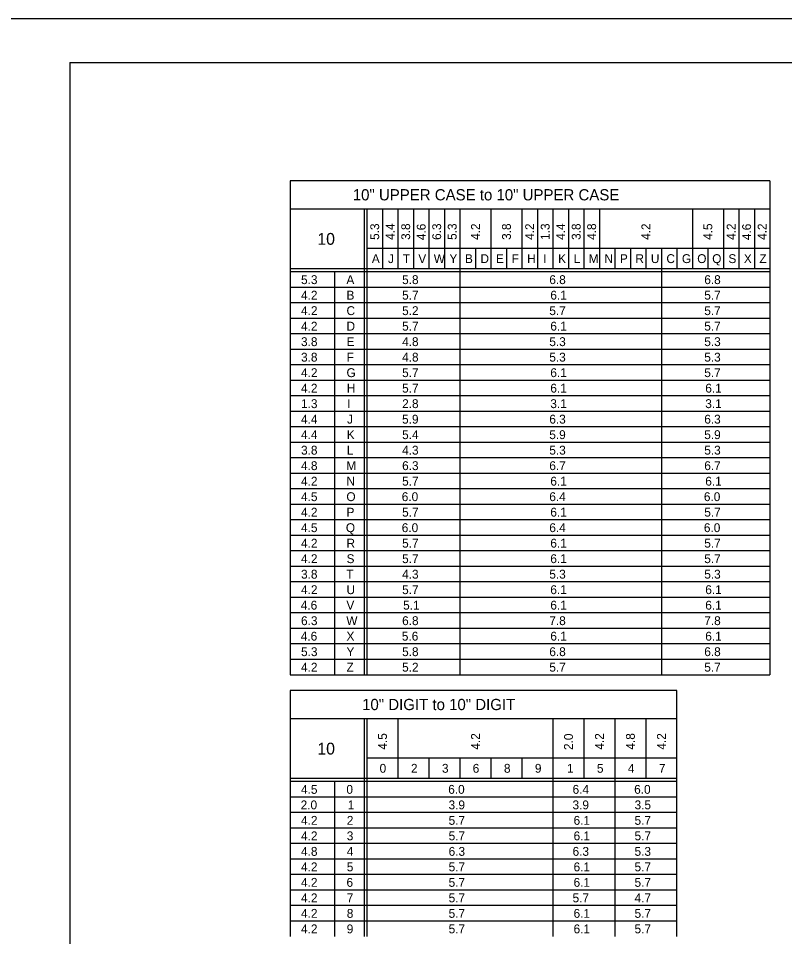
# Model space of a CAD drawing. Extents: x 637580 to 641849, y 297270 to 299646.
# Drawn here: x 640966.8 to 641226.4, y 299334.6 to 299645.6 of the extents above; entities that cross this region are included whole.
import ezdxf

# ---------------------------------------------------------------- set-up
doc = ezdxf.new("R2010")
doc.units = 0
for name, color, linetype in [('1', 7, 'Continuous'), ('2', 7, 'Continuous'), ('XCS-GRID-HVGL', 7, 'Continuous')]:
    doc.layers.add(name, color=color, linetype=linetype)

msp = doc.modelspace()

# ---------------------------------------------------------------- linework, layer by layer
at = {"layer": '1'}
for q in [(641770.31, 299630.63), (640984.31, 299066.63)]:
    msp.add_line((640984.31, 299630.63), q, dxfattribs=at)
at = {"layer": '2'}
for p, q in [((641221.44, 299590.63), (641058.94, 299590.63)), ((641058.94, 299590.63), (641058.94, 299423.25)), ((641221.44, 299590.63), (641221.44, 299423.25)), ((641058.94, 299581.13), (641221.44, 299581.13)), ((641083.94, 299581.13), (641083.94, 299423.25)), ((641084.94, 299581.13), (641084.94, 299423.25)), ((641090.19, 299581.13), (641090.19, 299560.75)), ((641095.44, 299581.13), (641095.44, 299560.75)), ((641100.69, 299581.13), (641100.69, 299560.75)), ((641105.94, 299581.13), (641105.94, 299560.75)), ((641111.19, 299581.13), (641111.19, 299560.75)), ((641116.44, 299581.13), (641116.44, 299423.25)), ((641126.94, 299581.13), (641126.94, 299560.75)), ((641137.44, 299581.13), (641137.44, 299560.75)), ((641142.69, 299581.13), (641142.69, 299560.75)), ((641147.94, 299581.13), (641147.94, 299560.75)), ((641153.19, 299581.13), (641153.19, 299560.75)), ((641158.44, 299581.13), (641158.44, 299560.75)), ((641163.69, 299581.13), (641163.69, 299560.75)), ((641195.19, 299581.13), (641195.19, 299560.75)), ((641205.69, 299581.13), (641205.69, 299560.75)), ((641210.94, 299581.13), (641210.94, 299560.75)), ((641216.19, 299581.13), (641216.19, 299560.75)), ((641084.94, 299567.75), (641221.44, 299567.75)), ((641121.69, 299567.75), (641121.69, 299560.75)), ((641132.19, 299567.75), (641132.19, 299560.75)), ((641168.94, 299567.75), (641168.94, 299560.75)), ((641174.19, 299567.75), (641174.19, 299560.75)), ((641179.44, 299567.75), (641179.44, 299560.75)), ((641179.44, 299567.75), (641179.44, 299560.75)), ((641184.69, 299567.75), (641184.69, 299423.25)), ((641189.94, 299567.75), (641189.94, 299560.75)), ((641200.44, 299567.75), (641200.44, 299560.75)), ((641221.44, 299560.75), (641058.94, 299560.75)), ((641221.44, 299559.75), (641058.94, 299559.75)), ((641073.94, 299559.75), (641073.94, 299423.25)), ((641221.44, 299554.5), (641058.94, 299554.5)), ((641221.44, 299549.25), (641058.94, 299549.25)), ((641221.44, 299544), (641058.94, 299544)), ((641221.44, 299538.75), (641058.94, 299538.75)), ((641221.44, 299533.5), (641058.94, 299533.5)), ((641221.44, 299528.25), (641058.94, 299528.25)), ((641221.44, 299523), (641058.94, 299523)), ((641221.44, 299517.75), (641058.94, 299517.75)), ((641221.44, 299512.5), (641058.94, 299512.5)), ((641221.44, 299507.25), (641058.94, 299507.25)), ((641221.44, 299502), (641058.94, 299502)), ((641221.44, 299496.75), (641058.94, 299496.75)), ((641221.44, 299491.5), (641058.94, 299491.5)), ((641221.44, 299486.25), (641058.94, 299486.25)), ((641221.44, 299481), (641058.94, 299481)), ((641221.44, 299475.75), (641058.94, 299475.75)), ((641221.44, 299470.5), (641058.94, 299470.5)), ((641221.44, 299465.25), (641058.94, 299465.25)), ((641221.44, 299460), (641058.94, 299460)), ((641221.44, 299454.75), (641058.94, 299454.75)), ((641221.44, 299449.5), (641058.94, 299449.5)), ((641221.44, 299444.25), (641058.94, 299444.25)), ((641221.44, 299439), (641058.94, 299439)), ((641221.44, 299433.75), (641058.94, 299433.75)), ((641221.44, 299428.5), (641058.94, 299428.5)), ((641058.94, 299423.25), (641058.94, 299423.25)), ((641058.94, 299423.25), (641221.44, 299423.25)), ((641189.94, 299418), (641058.94, 299418)), ((641058.94, 299418), (641058.94, 299334.63)), ((641189.94, 299334.63), (641189.94, 299418)), ((641058.94, 299408.5), (641189.94, 299408.5)), ((641083.94, 299408.5), (641083.94, 299334.63)), ((641084.94, 299408.5), (641084.94, 299334.63)), ((641095.44, 299408.5), (641095.44, 299388.13)), ((641147.94, 299408.5), (641147.94, 299334.63)), ((641158.44, 299408.5), (641158.44, 299388.13)), ((641168.94, 299408.5), (641168.94, 299334.63)), ((641179.44, 299408.5), (641179.44, 299388.13)), ((641084.94, 299395.13), (641189.94, 299395.13)), ((641105.94, 299395.13), (641105.94, 299388.13)), ((641116.44, 299395.13), (641116.44, 299388.13)), ((641126.94, 299395.13), (641126.94, 299388.13)), ((641137.44, 299395.13), (641137.44, 299388.13)), ((641189.94, 299388.13), (641058.94, 299388.13)), ((641189.94, 299387.13), (641058.94, 299387.13)), ((641073.94, 299387.13), (641073.94, 299334.63)), ((641189.94, 299381.88), (641058.94, 299381.88)), ((641189.94, 299376.63), (641058.94, 299376.63)), ((641189.94, 299371.38), (641058.94, 299371.38)), ((641189.94, 299366.13), (641058.94, 299366.13)), ((641189.94, 299360.88), (641058.94, 299360.88)), ((641189.94, 299355.63), (641058.94, 299355.63)), ((641189.94, 299350.38), (641058.94, 299350.38)), ((641189.94, 299345.13), (641058.94, 299345.13)), ((641189.94, 299339.88), (641058.94, 299339.88))]:
    msp.add_line(p, q, dxfattribs=at)
at = {"layer": 'XCS-GRID-HVGL'}
msp.add_lwpolyline([(640944.31, 299645.63), (641785.31, 299645.63), (641785.31, 299051.63), (640944.31, 299051.63)], close=True, dxfattribs=at)

# ---------------------------------------------------------------- texts
at = {"layer": '2'}
for s, height, p in [('10" UPPER CASE to 10" UPPER CASE', 3.8, (641080.12, 299583.98)), ('10', 4, (641068.13, 299568.94)), ('A', 3, (641086.58, 299562.75)), ('J', 3, (641092.07, 299562.75)), ('T', 3, (641097.07, 299562.75)), ('V', 3, (641102.33, 299562.75)), ('W', 3, (641107.56, 299562.75)), ('Y', 3, (641112.87, 299562.75)), ('B', 3, (641118.13, 299562.75)), ('D', 3, (641123.38, 299562.75)), ('E', 3, (641128.64, 299562.75)), ('F', 3, (641133.95, 299562.75)), ('H', 3, (641139.21, 299562.75)), ('I', 3, (641144.63, 299562.75)), ('K', 3, (641149.71, 299562.75)), ('L', 3, (641154.96, 299562.75)), ('M', 3, (641160.06, 299562.75)), ('N', 3, (641165.38, 299562.75)), ('P', 3, (641170.63, 299562.75)), ('R', 3, (641175.88, 299562.75)), ('U', 3, (641181.12, 299562.75)), ('C', 3, (641186.38, 299562.75)), ('G', 3, (641191.63, 299562.75)), ('O', 3, (641196.83, 299562.75)), ('Q', 3, (641201.9, 299562.75)), ('S', 3, (641207.39, 299562.75)), ('X', 3, (641212.62, 299562.75)), ('Z', 3, (641217.88, 299562.75)), ('5.3', 3, (641062.59, 299555.63)), ('A', 3, (641077.96, 299555.63)), ('5.8', 3, (641096.84, 299555.63)), ('6.8', 3, (641146.71, 299555.63)), ('6.8', 3, (641199.21, 299555.63)), ('4.2', 3, (641062.59, 299550.38)), ('B', 3, (641078, 299550.38)), ('5.7', 3, (641096.84, 299550.38)), ('6.1', 3, (641147.05, 299550.38)), ('5.7', 3, (641199.21, 299550.38)), ('4.2', 3, (641062.59, 299545.13)), ('C', 3, (641078, 299545.13)), ('5.2', 3, (641096.84, 299545.13)), ('5.7', 3, (641146.71, 299545.13)), ('5.7', 3, (641199.21, 299545.13)), ('4.2', 3, (641062.59, 299539.88)), ('D', 3, (641078, 299539.88)), ('5.7', 3, (641096.84, 299539.88)), ('6.1', 3, (641147.05, 299539.88)), ('5.7', 3, (641199.21, 299539.88)), ('3.8', 3, (641062.59, 299534.63)), ('E', 3, (641078.02, 299534.63)), ('4.8', 3, (641096.84, 299534.63)), ('5.3', 3, (641146.71, 299534.63)), ('5.3', 3, (641199.21, 299534.63)), ('3.8', 3, (641062.59, 299529.38)), ('F', 3, (641078.07, 299529.38)), ('4.8', 3, (641096.84, 299529.38)), ('5.3', 3, (641146.71, 299529.38)), ('5.3', 3, (641199.21, 299529.38)), ('4.2', 3, (641062.59, 299524.13)), ('G', 3, (641078, 299524.13)), ('5.7', 3, (641096.84, 299524.13)), ('6.1', 3, (641147.05, 299524.13)), ('5.7', 3, (641199.21, 299524.13)), ('4.2', 3, (641062.59, 299518.88)), ('H', 3, (641078.09, 299518.88)), ('5.7', 3, (641096.84, 299518.88)), ('6.1', 3, (641147.05, 299518.88)), ('6.1', 3, (641199.55, 299518.88)), ('1.3', 3, (641062.59, 299513.63)), ('I', 3, (641078.25, 299513.63)), ('2.8', 3, (641096.84, 299513.63)), ('3.1', 3, (641147.05, 299513.63)), ('3.1', 3, (641199.55, 299513.63)), ('4.4', 3, (641062.59, 299508.38)), ('J', 3, (641078.19, 299508.38)), ('5.9', 3, (641096.82, 299508.38)), ('6.3', 3, (641146.71, 299508.38)), ('6.3', 3, (641199.21, 299508.38)), ('4.4', 3, (641062.59, 299503.13)), ('K', 3, (641078.09, 299503.13)), ('5.4', 3, (641096.84, 299503.13)), ('5.9', 3, (641146.7, 299503.13)), ('5.9', 3, (641199.2, 299503.13)), ('3.8', 3, (641062.59, 299497.88)), ('L', 3, (641078.09, 299497.88)), ('4.3', 3, (641096.84, 299497.88)), ('5.3', 3, (641146.71, 299497.88)), ('5.3', 3, (641199.21, 299497.88)), ('4.8', 3, (641062.59, 299492.63)), ('M', 3, (641077.93, 299492.63)), ('6.3', 3, (641096.84, 299492.63)), ('6.7', 3, (641146.71, 299492.63)), ('6.7', 3, (641199.21, 299492.63)), ('4.2', 3, (641062.59, 299487.38)), ('N', 3, (641078, 299487.38)), ('5.7', 3, (641096.84, 299487.38)), ('6.1', 3, (641147.05, 299487.38)), ('6.1', 3, (641199.55, 299487.38)), ('4.5', 3, (641062.59, 299482.13)), ('O', 3, (641077.96, 299482.13)), ('6.0', 3, (641096.71, 299482.13)), ('6.4', 3, (641146.71, 299482.13)), ('6.0', 3, (641199.08, 299482.13)), ('4.2', 3, (641062.59, 299476.88)), ('P', 3, (641078, 299476.88)), ('5.7', 3, (641096.84, 299476.88)), ('6.1', 3, (641147.05, 299476.88)), ('5.7', 3, (641199.21, 299476.88)), ('4.5', 3, (641062.59, 299471.63)), ('Q', 3, (641077.78, 299471.63)), ('6.0', 3, (641096.71, 299471.63)), ('6.4', 3, (641146.71, 299471.63)), ('6.0', 3, (641199.08, 299471.63)), ('4.2', 3, (641062.59, 299466.38)), ('R', 3, (641078, 299466.38)), ('5.7', 3, (641096.84, 299466.38)), ('6.1', 3, (641147.05, 299466.38)), ('5.7', 3, (641199.21, 299466.38)), ('4.2', 3, (641062.59, 299461.13)), ('S', 3, (641078.02, 299461.13)), ('5.7', 3, (641096.84, 299461.13)), ('6.1', 3, (641147.05, 299461.13)), ('5.7', 3, (641199.21, 299461.13)), ('3.8', 3, (641062.59, 299455.88)), ('T', 3, (641077.94, 299455.88)), ('4.3', 3, (641096.84, 299455.88)), ('5.3', 3, (641146.71, 299455.88)), ('5.3', 3, (641199.21, 299455.88)), ('4.2', 3, (641062.59, 299450.63)), ('U', 3, (641077.99, 299450.63)), ('5.7', 3, (641096.84, 299450.63)), ('6.1', 3, (641147.05, 299450.63)), ('6.1', 3, (641199.55, 299450.63)), ('4.6', 3, (641062.5, 299445.38)), ('V', 3, (641077.96, 299445.38)), ('5.1', 3, (641097.18, 299445.38)), ('6.1', 3, (641147.05, 299445.38)), ('6.1', 3, (641199.55, 299445.38)), ('6.3', 3, (641062.59, 299440.13)), ('W', 3, (641077.93, 299440.13)), ('6.8', 3, (641096.84, 299440.13)), ('7.8', 3, (641146.71, 299440.13)), ('7.8', 3, (641199.21, 299440.13)), ('4.6', 3, (641062.5, 299434.88)), ('X', 3, (641077.99, 299434.88)), ('5.6', 3, (641096.75, 299434.88)), ('6.1', 3, (641147.05, 299434.88)), ('6.1', 3, (641199.55, 299434.88)), ('5.3', 3, (641062.59, 299429.63)), ('Y', 3, (641077.99, 299429.63)), ('5.8', 3, (641096.84, 299429.63)), ('6.8', 3, (641146.71, 299429.63)), ('6.8', 3, (641199.21, 299429.63)), ('4.2', 3, (641062.59, 299424.38)), ('Z', 3, (641078, 299424.38)), ('5.2', 3, (641096.84, 299424.38)), ('5.7', 3, (641146.71, 299424.38)), ('5.7', 3, (641199.21, 299424.38)), ('10" DIGIT to 10" DIGIT', 3.8, (641083.28, 299411.35)), ('10', 4, (641068.13, 299396.31)), ('0', 3, (641089.21, 299390.13)), ('2', 3, (641099.84, 299390.13)), ('3', 3, (641110.34, 299390.13)), ('6', 3, (641120.75, 299390.13)), ('8', 3, (641131.34, 299390.13)), ('9', 3, (641141.82, 299390.13)), ('1', 3, (641152.68, 299390.13)), ('5', 3, (641162.84, 299390.13)), ('4', 3, (641173.34, 299390.13)), ('7', 3, (641183.84, 299390.13)), ('4.5', 3, (641062.59, 299383)), ('0', 3, (641077.96, 299383)), ('6.0', 3, (641112.46, 299383)), ('6.4', 3, (641154.59, 299383)), ('6.0', 3, (641175.46, 299383)), ('2.0', 3, (641062.46, 299377.75)), ('1', 3, (641078.43, 299377.75)), ('3.9', 3, (641112.57, 299377.75)), ('3.9', 3, (641154.57, 299377.75)), ('3.5', 3, (641175.59, 299377.75)), ('4.2', 3, (641062.59, 299372.5)), ('2', 3, (641078.09, 299372.5)), ('5.7', 3, (641112.59, 299372.5)), ('6.1', 3, (641154.93, 299372.5)), ('5.7', 3, (641175.59, 299372.5)), ('4.2', 3, (641062.59, 299367.25)), ('3', 3, (641078.09, 299367.25)), ('5.7', 3, (641112.59, 299367.25)), ('6.1', 3, (641154.93, 299367.25)), ('5.7', 3, (641175.59, 299367.25)), ('4.8', 3, (641062.59, 299362)), ('4', 3, (641078.09, 299362)), ('6.3', 3, (641112.59, 299362)), ('6.3', 3, (641154.59, 299362)), ('5.3', 3, (641175.59, 299362)), ('4.2', 3, (641062.59, 299356.75)), ('5', 3, (641078.09, 299356.75)), ('5.7', 3, (641112.59, 299356.75)), ('6.1', 3, (641154.93, 299356.75)), ('5.7', 3, (641175.59, 299356.75)), ('4.2', 3, (641062.59, 299351.5)), ('6', 3, (641078, 299351.5)), ('5.7', 3, (641112.59, 299351.5)), ('6.1', 3, (641154.93, 299351.5)), ('5.7', 3, (641175.59, 299351.5)), ('4.2', 3, (641062.59, 299346.25)), ('7', 3, (641078.09, 299346.25)), ('5.7', 3, (641112.59, 299346.25)), ('5.7', 3, (641154.59, 299346.25)), ('4.7', 3, (641175.59, 299346.25)), ('4.2', 3, (641062.59, 299341)), ('8', 3, (641078.09, 299341)), ('5.7', 3, (641112.59, 299341)), ('6.1', 3, (641154.93, 299341)), ('5.7', 3, (641175.59, 299341)), ('4.2', 3, (641062.59, 299335.75)), ('9', 3, (641078.07, 299335.75)), ('5.7', 3, (641112.59, 299335.75)), ('6.1', 3, (641154.93, 299335.75)), ('5.7', 3, (641175.59, 299335.75))]:
    msp.add_text(s, height=height, dxfattribs=at).set_placement(p)
for s, p in [('5.3', (641089.06, 299570.59)), ('4.4', (641094.31, 299570.59)), ('3.8', (641099.56, 299570.59)), ('4.6', (641104.81, 299570.51)), ('6.3', (641110.06, 299570.59)), ('5.3', (641115.31, 299570.59)), ('4.2', (641123.19, 299570.59)), ('3.8', (641133.69, 299570.59)), ('4.2', (641141.56, 299570.59)), ('1.3', (641146.81, 299570.59)), ('4.4', (641152.06, 299570.59)), ('3.8', (641157.31, 299570.59)), ('4.8', (641162.56, 299570.59)), ('4.2', (641180.94, 299570.59)), ('4.5', (641201.94, 299570.59)), ('4.2', (641209.81, 299570.59)), ('4.6', (641215.06, 299570.51)), ('4.2', (641220.31, 299570.59)), ('4.5', (641091.69, 299397.96)), ('4.2', (641123.19, 299397.96)), ('2.0', (641154.69, 299397.83)), ('4.2', (641165.19, 299397.96)), ('4.8', (641175.69, 299397.96)), ('4.2', (641186.19, 299397.96))]:
    msp.add_text(s, height=3, rotation=90, dxfattribs=at).set_placement(p)

doc.saveas('drawing.dxf')
